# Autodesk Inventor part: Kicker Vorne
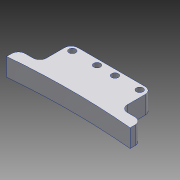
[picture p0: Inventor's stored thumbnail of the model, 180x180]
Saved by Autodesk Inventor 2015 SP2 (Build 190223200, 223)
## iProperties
Created: 2012-07
Part Number: Kicker Vorne
Material: Aluminium 6061
Document SubType Name: Modeling
Designer: rYan
Mass: 19.1529 g
Surface Area: 33.2838 cm^2
Volume: 7.0675 cm^3
Density: 2.71 g/cm^3
Appearance: Aluminium - flach
Author: rYan
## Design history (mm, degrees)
sketch "Skizze1"
  geometry: L1 (27.5, -14)-(27.5, -19.263); L2 (-27.5, -14)-(-27.5, -19.263); L3 (0, 63.6)-(0, -381.6) reference; L4 (-38.5, 0)-(38.5, 0) reference; L5 (27.5, -18)-(-27.5, -18); L6 (-18, 0)-(18, 0); L7 (18, 0)-(18, -14); L8 (-18, -14)-(-18, 0); L9 (-27.5, -14)-(-18, -14); L10 (18, -14)-(27.5, -14); A1 r 300 centre (0, -318) between (27.5, -19.263) and (-27.5, -19.263); 1 further point
  constraints: 16 end point, 4 perpendicular, 3 horizontal, 3 point on line, 2 parallel, 2 point on circle, 1 centre point, 1 symmetric about line, 1 tangent, 3 other
  dimensions: "d0" = 55 distance of L2.start L1.start; "d2" = 300 radius of A1; "d56" = 36 distance between parallel lines of L7 L8; "d57" = 14 distance of L6.end L7.end; "d100" = 4 distance between parallel lines of L5 L10
extrude "Extrusion1" new body sketch "Skizze1" distance "d4" = 8; taper "d5" = 0 deg
sketch "Skizze12"
  geometry: L1 (0, 3.853)-(0, -23.116) reference; L2 (-38.5, 0)-(38.5, 0) reference; L3 (15, -2.5)-(-15, -2.5); 5 further points
  constraints: 2 coincident, 2 end point, 2 point on line, 2 symmetric about line, 1 horizontal
  dimensions: "d68" = 2.5 distance between parallel lines of L2 L3; "d69" = 30 distance of point (-15, -2.5) point (15, -2.5); "d99" = 8 distance of point (4, -2.5) point (-4, -2.5)
hole "Bohrung2" sketch "Skizze12" at (15, -2.5), (-15, -2.5), (-4, -2.5), (4, -2.5) diameter "d70" = 3; stored, may be unused: countersink angle "d74" = 90 deg, drill point angle "d76" = 118 deg; dims "d71" = 6, "d72" = 4, "d73" = 2, "d75" = 8
fillet "Rundung4" dims "d78" = 3
node "Volumenkörper1"
